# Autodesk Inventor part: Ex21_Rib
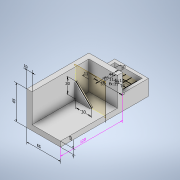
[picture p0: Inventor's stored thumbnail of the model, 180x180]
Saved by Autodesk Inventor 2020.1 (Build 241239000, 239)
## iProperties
Created: 2019-11
Part Number: Ex21_Rib
Material: Generic
Document SubType Name: Modeling
Designer: Synergysoft Dell02
Density: 1 g/cm^3
Appearance: Default
Author: Synergysoft Dell02
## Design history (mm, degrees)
node "Annotations"
  node "Linear Dimension 1" dims "d43" = 65 (derived)
  node "Linear Dimension 2" dims "d46" = 65 (derived)
  node "Linear Dimension 3" dims "d49" = 10 (derived)
  node "Linear Dimension 4" dims "d52" = 10 (derived)
  node "Linear Dimension 5" dims "d53" = 120 (derived)
  node "Linear Dimension 6" dims "d56" = 25 (derived)
sketch "Sketch1"
  geometry: L1 (0, 0)-(0, 65); L2 (0, 65)-(10, 65); L3 (10, 65)-(10, 10); L4 (10, 10)-(65, 10); L5 (65, 10)-(65, 0); L6 (65, 0)-(0, 0); L7 (10, 65)-(65, 65); L8 (65, 65)-(65, 10)
  constraints: 16 end point, 5 perpendicular, 1 collinear, 1 horizontal, 1 vertical
  dimensions: "d0" = 65 distance of L1.start L1.end; "d1" = 10 distance of L1.end L2.end; "d39" = 65 distance between parallel lines of L5 L1; "d40" = 10 distance of L4.end L5.end
extrude "Extrusion1" new body sketch "Sketch1" distance "d5" = 120; taper "d6" = 0 deg
extrude "Extrusion2" join sketch "Sketch1" distance "d7" = 10 (= d1); taper "d8" = 0 deg
workplane "Work Plane4"
  workplane "Work Plane3"
sketch "Sketch2"
  geometry: L1 (10, 40)-(40, 10); L2 (65, 10)-(10, 10) reference; L3 (10, 10)-(10, 65) reference; 1 further point
  constraints: 2 end point, 2 point on line
  dimensions: "d12" = 30 distance from line of L2 L1.start; "d13" = 30 distance from line of L1.end L3
feature "Rib1" sketch "Sketch2" dims "d14" = 5, "d15" = 5, "d16" = 0, "d17" = 0, "d18" = 1, "d19" = 1
sketch "Sketch6"
  geometry: L1 (-65, 10)-(-65, 65) reference; L2 (-65, 30)-(0, 30); L3 (0, 30)-(0, 0); L4 (0, 0)-(-65, 0); L5 (-65, 0)-(-65, 30); 1 further point
  constraints: 8 end point, 2 parallel, 1 horizontal, 1 perpendicular, 1 point on line
  dimensions: "d57" = 30 distance between parallel lines of L4 L2
extrude "Extrusion3" join sketch "Sketch6" distance "d58" = 50; taper "d59" = 0 deg
shell "Shell1" dims "d60" = 10, "d61" = 6
workplane "Work Plane5"
sketch "Sketch7"
  geometry: L1 (-2, 11)-(53, 11); L2 (59, 0)-(-6, 0) reference; L3 (-2, 22)-(53, 22); L4 (-2, 33)-(53, 33); L5 (53, 44)-(53, 0) reference; L6 (-1.5, 46)-(53.5, 46); L7 (10, 0)-(10, 44); L8 (0, 0)-(0, 44) reference; L9 (21, 0)-(21, 44); L10 (32, 0)-(32, 44); L11 (43, 0)-(43, 44)
  constraints: 16 end point, 8 parallel, 3 point on line, 1 horizontal, 1 midpoint, 1 vertical
  dimensions: "d63" = 55 distance of L1.start L1.end; "d64" = 11 distance between parallel lines of L1 L2; "d65" = 11 distance between parallel lines of L1 L3 (= d64); "d66" = 11 distance between parallel lines of L3 L4 (= d64); "d68" = 44 distance of L7.start L7.end; "d69" = 10 distance between parallel lines of L7 L8; "d70" = 11 distance between parallel lines of L7 L9; "d71" = 11 distance between parallel lines of L9 L10; "d72" = 11 distance between parallel lines of L10 L11
sketch "Sketch3"
  geometry: L1 (10, 40)-(40, 10) reference; 1 further point
feature "Rib2" sketch "Sketch3" dims "d20" = 5, "d21" = 5, "d22" = 0, "d23" = 0, "d24" = 1, "d25" = 1
sketch "Sketch4"
  geometry: L1 (10, 40)-(40, 10) reference; 1 further point
feature "Rib3" sketch "Sketch4" dims "d26" = 5, "d27" = 5, "d28" = 0, "d29" = 0, "d30" = 1, "d31" = 1
sketch "Sketch5"
  geometry: L1 (10, 40)-(40, 10) reference; 1 further point
feature "Rib4" sketch "Sketch5" dims "d33" = 5, "d34" = 5, "d35" = 0, "d36" = 0, "d37" = 1, "d38" = 1
body "Solid1"
workplane "Work Plane1"
workplane "Work Plane2"
other parameters: "d9" = 25, "d10" = 25, "d11" = 25, "d32" = 25, "d62" = 15, "d41" = 0 (derived), "d44" = 0 (derived), "d47" = 0 (derived), "d50" = 0 (derived), "d54" = 67.75 (derived), "d55" = 22.13259 (derived)
